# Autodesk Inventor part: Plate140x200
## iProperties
Created: 2006-02
Part Number: Plate140x200
Document SubType Name: Modeling
Designer: 40664
Mass: 275.476 g
Surface Area: 634.032 cm^2
Volume: 275.476 cm^3
Density: 1 g/cm^3
CSToolsMass: 0.3
CSToolsVolume: 275476.0
CSToolsArea: 634.0
Author: 40664
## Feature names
1. Extrusion1
2. Hole2
